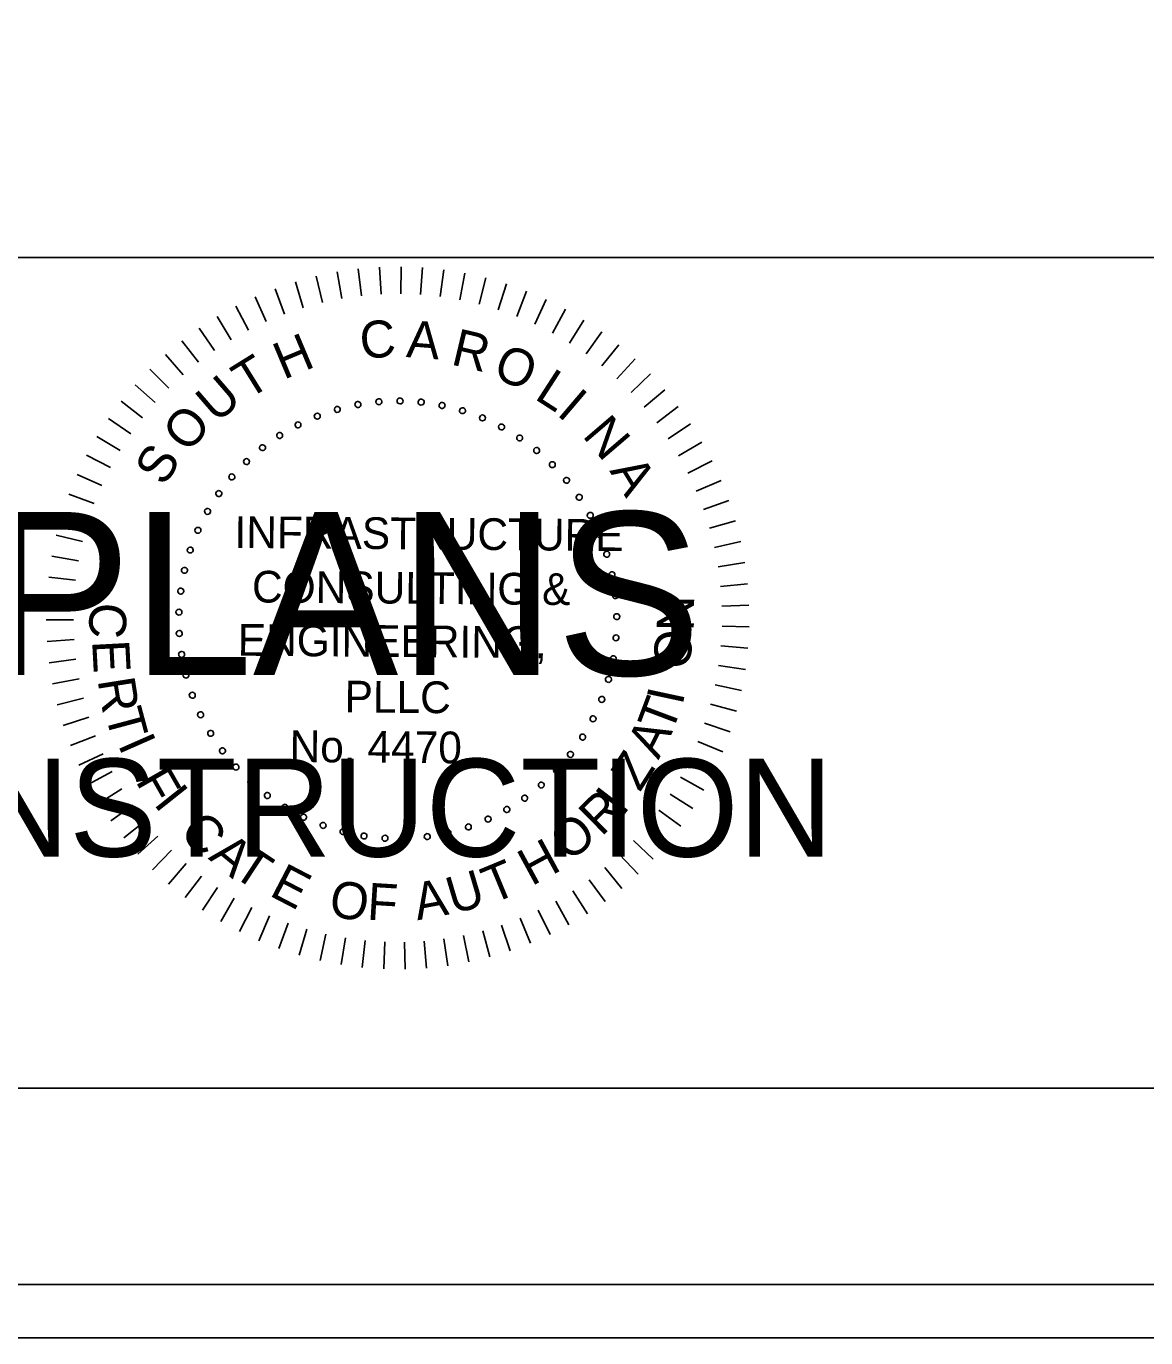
# Model space of a CAD drawing. Extents: x 967 to 1326, y 964 to 3144.
# Drawn here: x 1189.3 to 1212.88, y 2363.72 to 2391.36 of the extents above; entities that cross this region are included whole.
import ezdxf

# ---------------------------------------------------------------- set-up
doc = ezdxf.new("R2010")
doc.units = 0
for name, color, linetype in [('RD_XS_EwShp', 7, 'Continuous'), ('RD_XS_ExPaveRet', 7, 'Continuous'), ('RD_XS_TX_Elev_EX', 7, 'Continuous'), ('RD_XS_TX_Elev_PR', 7, 'Continuous'), ('RD_XS_TX_Station', 7, 'Continuous')]:
    doc.layers.add(name, color=color, linetype=linetype)

msp = doc.modelspace()

# ---------------------------------------------------------------- linework, layer by layer
at = {"layer": 'RD_XS_ExPaveRet'}
for points in [[(967.409, 2363.72), (1326.285, 2363.72), (1326.285, 2583.72), (967.409, 2583.72)], [(988.525, 2364.84), (1326.285, 2364.84), (1326.285, 2582.6), (988.525, 2582.6)]]:
    msp.add_lwpolyline(points, close=True, dxfattribs=at)
at = {"layer": 'RD_XS_TX_Elev_EX'}
for p, q in [((996.114, 2386.486), (1323.886, 2386.486)), ((1323.886, 2368.983), (996.114, 2368.983))]:
    msp.add_line(p, q, dxfattribs=at)
at = {"layer": 'RD_XS_TX_Elev_PR'}
for p, q in [((1195.846, 2386.181), (1195.945, 2385.62)), ((1196.292, 2386.245), (1196.357, 2385.68)), ((1196.742, 2386.282), (1196.772, 2385.714)), ((1197.194, 2386.292), (1197.189, 2385.723)), ((1197.645, 2386.274), (1197.606, 2385.706)), ((1198.094, 2386.228), (1198.02, 2385.664)), ((1198.54, 2386.156), (1198.432, 2385.596)), ((1194.968, 2385.971), (1195.134, 2385.427)), ((1195.403, 2386.09), (1195.536, 2385.536)), ((1198.98, 2386.056), (1198.838, 2385.504)), ((1199.414, 2385.929), (1199.238, 2385.387)), ((1194.122, 2385.656), (1194.353, 2385.136)), ((1194.54, 2385.827), (1194.739, 2385.293)), ((1199.839, 2385.777), (1199.63, 2385.246)), ((1200.253, 2385.598), (1200.013, 2385.082)), ((1193.715, 2385.461), (1193.978, 2384.956)), ((1200.656, 2385.395), (1200.385, 2384.894)), ((1193.321, 2385.241), (1193.614, 2384.752)), ((1201.047, 2385.167), (1200.745, 2384.684)), ((1192.94, 2384.997), (1193.263, 2384.528)), ((1201.422, 2384.917), (1201.092, 2384.453)), ((1192.576, 2384.731), (1192.926, 2384.282)), ((1201.781, 2384.643), (1201.424, 2384.2)), ((1192.228, 2384.443), (1192.605, 2384.016)), ((1202.124, 2384.349), (1201.739, 2383.928)), ((1191.899, 2384.134), (1192.301, 2383.731)), ((1202.447, 2384.034), (1202.038, 2383.638)), ((1191.589, 2383.805), (1192.015, 2383.428)), ((1202.751, 2383.7), (1202.318, 2383.329)), ((1191.299, 2383.459), (1191.748, 2383.108)), ((1203.034, 2383.348), (1202.579, 2383.004)), ((1191.032, 2383.095), (1191.501, 2382.772)), ((1203.294, 2382.979), (1202.82, 2382.664)), ((1190.787, 2382.716), (1191.274, 2382.422)), ((1203.532, 2382.595), (1203.04, 2382.31)), ((1190.565, 2382.323), (1191.07, 2382.059)), ((1203.746, 2382.198), (1203.237, 2381.943)), ((1190.368, 2381.916), (1190.888, 2381.684)), ((1203.936, 2381.788), (1203.412, 2381.564)), ((1190.196, 2381.499), (1190.729, 2381.299)), ((1204.1, 2381.367), (1203.563, 2381.176)), ((1190.05, 2381.072), (1190.594, 2380.905)), ((1204.238, 2380.937), (1203.691, 2380.779)), ((1189.93, 2380.636), (1190.484, 2380.503)), ((1204.349, 2380.5), (1203.794, 2380.375)), ((1189.837, 2380.195), (1190.398, 2380.095)), ((1204.434, 2380.056), (1203.872, 2379.966)), ((1189.771, 2379.748), (1190.337, 2379.683)), ((1204.491, 2379.608), (1203.925, 2379.552)), ((1189.732, 2379.298), (1190.301, 2379.267)), ((1204.522, 2379.158), (1203.953, 2379.137)), ((1189.721, 2378.847), (1190.29, 2378.851)), ((1204.524, 2378.706), (1203.955, 2378.72)), ((1189.737, 2378.396), (1190.306, 2378.434)), ((1204.499, 2378.256), (1203.932, 2378.304)), ((1189.781, 2377.946), (1190.346, 2378.019)), ((1204.447, 2377.807), (1203.884, 2377.89)), ((1189.852, 2377.5), (1190.412, 2377.608)), ((1204.367, 2377.363), (1203.81, 2377.479)), ((1189.951, 2377.06), (1190.502, 2377.201)), ((1204.261, 2376.924), (1203.712, 2377.074)), ((1190.076, 2376.626), (1190.617, 2376.8)), ((1204.128, 2376.492), (1203.589, 2376.676)), ((1190.227, 2376.2), (1190.757, 2376.408)), ((1203.969, 2376.07), (1203.442, 2376.286)), ((1190.403, 2375.785), (1190.92, 2376.024)), ((1190.605, 2375.381), (1191.106, 2375.651)), ((1203.784, 2375.658), (1203.271, 2375.906)), ((1203.574, 2375.258), (1203.078, 2375.537)), ((1190.831, 2374.99), (1191.315, 2375.291)), ((1203.341, 2374.871), (1202.862, 2375.18)), ((1191.081, 2374.614), (1191.545, 2374.943)), ((1203.085, 2374.5), (1202.626, 2374.837)), ((1191.353, 2374.253), (1191.796, 2374.61)), ((1191.646, 2373.91), (1192.067, 2374.293)), ((1202.806, 2374.145), (1202.368, 2374.509)), ((1191.96, 2373.585), (1192.356, 2373.994)), ((1202.506, 2373.807), (1202.092, 2374.197)), ((1192.293, 2373.28), (1192.664, 2373.712)), ((1202.186, 2373.488), (1201.796, 2373.903)), ((1192.644, 2372.996), (1192.988, 2373.45)), ((1201.847, 2373.19), (1201.484, 2373.628)), ((1193.011, 2372.734), (1193.327, 2373.208)), ((1201.491, 2372.912), (1201.155, 2373.372)), ((1193.394, 2372.495), (1193.68, 2372.987)), ((1200.731, 2372.425), (1200.453, 2372.922)), ((1201.119, 2372.657), (1200.811, 2373.136)), ((1193.791, 2372.279), (1194.047, 2372.788)), ((1194.2, 2372.088), (1194.424, 2372.612)), ((1200.331, 2372.217), (1200.083, 2372.73)), ((1194.62, 2371.923), (1194.812, 2372.459)), ((1195.05, 2371.783), (1195.208, 2372.33)), ((1199.495, 2371.877), (1199.312, 2372.416)), ((1199.918, 2372.034), (1199.702, 2372.561)), ((1195.487, 2371.67), (1195.612, 2372.225)), ((1195.93, 2371.584), (1196.021, 2372.146)), ((1196.377, 2371.524), (1196.434, 2372.091)), ((1196.828, 2371.493), (1196.85, 2372.062)), ((1197.279, 2371.488), (1197.267, 2372.058)), ((1197.73, 2371.512), (1197.683, 2372.079)), ((1198.179, 2371.562), (1198.097, 2372.126)), ((1198.624, 2371.64), (1198.508, 2372.198)), ((1199.063, 2371.745), (1198.913, 2372.295))]:
    msp.add_line(p, q, dxfattribs=at)
for centre, start, end in [((1196.285, 2383.388), 10.6038, 190.6038), ((1196.285, 2383.388), 190.6038, 10.6038), ((1196.727, 2383.447), 5.0653, 185.0653), ((1196.727, 2383.447), 185.0653, 5.0653), ((1197.172, 2383.464), 359.5268, 179.5268), ((1197.172, 2383.464), 179.5268, 359.5268), ((1197.617, 2383.438), 173.9884, 353.9884), ((1197.617, 2383.438), 353.9884, 173.9884), ((1198.057, 2383.369), 168.4499, 348.4499), ((1198.057, 2383.369), 348.4499, 168.4499), ((1195.429, 2383.142), 21.6807, 201.6807), ((1195.429, 2383.142), 201.6807, 21.6807), ((1195.851, 2383.285), 16.1422, 196.1422), ((1195.851, 2383.285), 196.1422, 16.1422), ((1198.489, 2383.258), 162.9114, 342.9114), ((1198.489, 2383.258), 342.9114, 162.9114), ((1198.908, 2383.106), 157.373, 337.373), ((1198.908, 2383.106), 337.373, 157.373), ((1195.023, 2382.958), 27.2191, 207.2191), ((1195.023, 2382.958), 207.2191, 27.2191), ((1199.31, 2382.914), 151.8345, 331.8345), ((1199.31, 2382.914), 331.8345, 151.8345), ((1194.637, 2382.736), 32.7576, 212.7576), ((1194.637, 2382.736), 212.7576, 32.7576), ((1199.692, 2382.684), 146.2961, 326.2961), ((1199.692, 2382.684), 326.2961, 146.2961), ((1194.274, 2382.478), 38.2961, 218.2961), ((1194.274, 2382.478), 218.2961, 38.2961), ((1200.05, 2382.419), 140.7576, 320.7576), ((1200.05, 2382.419), 320.7576, 140.7576), ((1193.937, 2382.186), 43.8345, 223.8345), ((1193.937, 2382.186), 223.8345, 43.8345), ((1200.38, 2382.12), 135.2191, 315.2191), ((1200.38, 2382.12), 315.2191, 135.2191), ((1193.63, 2381.862), 49.373, 229.373), ((1193.63, 2381.862), 229.373, 49.373), ((1200.68, 2381.79), 129.6807, 309.6807), ((1200.68, 2381.79), 309.6807, 129.6807), ((1193.356, 2381.511), 54.9114, 234.9114), ((1193.356, 2381.511), 234.9114, 54.9114), ((1200.947, 2381.433), 124.1422, 304.1422), ((1200.947, 2381.433), 304.1422, 124.1422), ((1193.117, 2381.135), 60.4499, 240.4499), ((1193.117, 2381.135), 240.4499, 60.4499), ((1201.179, 2381.052), 118.6038, 298.6038), ((1201.179, 2381.052), 298.6038, 118.6038), ((1192.915, 2380.737), 65.9884, 245.9884), ((1192.915, 2380.737), 245.9884, 65.9884), ((1201.372, 2380.651), 113.0653, 293.0653), ((1201.372, 2380.651), 293.0653, 113.0653), ((1192.753, 2380.322), 71.5268, 251.5268), ((1192.753, 2380.322), 251.5268, 71.5268), ((1201.526, 2380.233), 107.5268, 287.5268), ((1201.526, 2380.233), 287.5268, 107.5268), ((1192.632, 2379.894), 77.0653, 257.0653), ((1192.632, 2379.894), 257.0653, 77.0653), ((1201.638, 2379.801), 101.9884, 281.9884), ((1201.638, 2379.801), 281.9884, 101.9884), ((1192.552, 2379.455), 82.6038, 262.6038), ((1192.552, 2379.455), 262.6038, 82.6038), ((1201.709, 2379.361), 96.4499, 276.4499), ((1201.709, 2379.361), 276.4499, 96.4499), ((1192.515, 2379.011), 88.1422, 268.1422), ((1192.515, 2379.011), 268.1422, 88.1422), ((1201.737, 2378.917), 90.9114, 270.9114), ((1201.737, 2378.917), 270.9114, 90.9114), ((1192.522, 2378.565), 93.6807, 273.6807), ((1192.522, 2378.565), 273.6807, 93.6807), ((1201.721, 2378.471), 85.373, 265.373), ((1201.721, 2378.471), 265.373, 85.373), ((1192.571, 2378.122), 99.2191, 279.2191), ((1192.571, 2378.122), 279.2191, 99.2191), ((1201.663, 2378.029), 79.8345, 259.8345), ((1201.663, 2378.029), 259.8345, 79.8345), ((1192.662, 2377.686), 104.7576, 284.7576), ((1192.662, 2377.686), 284.7576, 104.7576), ((1201.563, 2377.595), 74.2961, 254.2961), ((1201.563, 2377.595), 254.2961, 74.2961), ((1192.796, 2377.261), 110.2961, 290.2961), ((1192.796, 2377.261), 290.2961, 110.2961), ((1201.42, 2377.173), 68.7576, 248.7576), ((1201.42, 2377.173), 248.7576, 68.7576), ((1192.97, 2376.851), 115.8345, 295.8345), ((1192.97, 2376.851), 295.8345, 115.8345), ((1201.238, 2376.766), 63.2191, 243.2191), ((1201.238, 2376.766), 243.2191, 63.2191), ((1193.182, 2376.459), 121.373, 301.373), ((1193.182, 2376.459), 301.373, 121.373), ((1201.018, 2376.379), 57.6807, 237.6807), ((1201.018, 2376.379), 237.6807, 57.6807), ((1193.432, 2376.09), 126.9114, 306.9114), ((1193.432, 2376.09), 306.9114, 126.9114), ((1200.761, 2376.014), 52.1422, 232.1422), ((1200.761, 2376.014), 232.1422, 52.1422), ((1193.715, 2375.746), 132.4499, 312.4499), ((1193.715, 2375.746), 312.4499, 132.4499), ((1200.47, 2375.677), 46.6038, 226.6038), ((1200.47, 2375.677), 226.6038, 46.6038), ((1194.031, 2375.431), 137.9884, 317.9884), ((1194.031, 2375.431), 317.9884, 137.9884), ((1200.148, 2375.369), 41.0653, 221.0653), ((1200.148, 2375.369), 221.0653, 41.0653), ((1194.376, 2375.149), 143.5268, 323.5268), ((1194.376, 2375.149), 323.5268, 143.5268), ((1199.798, 2375.093), 35.5268, 215.5268), ((1199.798, 2375.093), 215.5268, 35.5268), ((1194.746, 2374.901), 149.0653, 329.0653), ((1194.746, 2374.901), 329.0653, 149.0653), ((1199.422, 2374.853), 29.9884, 209.9884), ((1199.422, 2374.853), 209.9884, 29.9884), ((1195.139, 2374.69), 154.6038, 334.6038), ((1195.139, 2374.69), 334.6038, 154.6038), ((1195.55, 2374.517), 160.1422, 340.1422), ((1195.55, 2374.517), 340.1422, 160.1422), ((1198.611, 2374.486), 18.9114, 198.9114), ((1199.026, 2374.65), 24.4499, 204.4499), ((1199.026, 2374.65), 204.4499, 24.4499), ((1195.975, 2374.386), 165.6807, 345.6807), ((1195.975, 2374.386), 345.6807, 165.6807), ((1196.412, 2374.295), 171.2191, 351.2191), ((1196.412, 2374.295), 351.2191, 171.2191), ((1196.855, 2374.248), 356.7576, 176.7576), ((1197.301, 2374.243), 2.2961, 182.2961), ((1197.745, 2374.282), 7.8345, 187.8345), ((1197.745, 2374.282), 187.8345, 7.8345), ((1198.183, 2374.363), 13.373, 193.373), ((1198.183, 2374.363), 193.373, 13.373), ((1198.611, 2374.486), 198.9114, 18.9114), ((1196.855, 2374.248), 176.7576, 356.7576), ((1197.301, 2374.243), 182.2961, 2.2961)]:
    msp.add_arc(centre, 0.0627, start, end, dxfattribs=at)
at = {"layer": 'RD_XS_TX_Station'}
msp.add_lwpolyline([(967.409, 2363.72), (1326.285, 2363.72), (1326.285, 2583.72), (967.409, 2583.72)], close=True, dxfattribs=at)

# ---------------------------------------------------------------- texts
at = {"layer": 'RD_XS_EwShp'}
for s, height, p in [('FINAL PLANS', 3.4375, (1174.145, 2377.685)), ('NOT FOR CONSTRUCTION', 2.0625, (1170.901, 2373.86))]:
    msp.add_text(s, height=height, dxfattribs=at).set_placement(p)
at = {"layer": 'RD_XS_TX_Elev_PR'}
for s, height, rotation, p in [('C', 0.78, 4.7281, (1196.355, 2384.346)), ('A', 0.78, 355.6981, (1197.29, 2384.39)), ('H', 0.78, 22.7882, (1194.72, 2383.904)), ('R', 0.78, 346.6681, (1198.222, 2384.238)), ('O', 0.78, 337.638, (1199.096, 2383.972)), ('T', 0.78, 31.8182, (1193.961, 2383.478)), ('U', 0.78, 40.8482, (1193.306, 2382.976)), ('L', 0.78, 327.108, (1199.981, 2383.52)), ('I', 0.78, 319.578, (1200.451, 2383.182)), ('O', 0.78, 49.8782, (1192.707, 2382.341)), ('N', 0.78, 310.548, (1200.994, 2382.728)), ('S', 0.78, 58.9083, (1192.211, 2381.642)), ('A', 0.78, 301.5179, (1201.576, 2381.991)), ('INFRASTRUCTURE', 0.66873, 359.5268, (1193.682, 2380.367)), ('CONSULTING &', 0.66873, 359.5268, (1194.051, 2379.217)), ('N', 0.78, 89.2085, (1203.359, 2378.604)), ('C', 0.78, 267.025, (1190.646, 2379.227)), ('ENGINEERING,', 0.66873, 359.5268, (1193.751, 2378.095)), ('O', 0.78, 83.2085, (1203.26, 2377.786)), ('E', 0.78, 273.025, (1190.685, 2378.408)), ('R', 0.78, 279.025, (1190.799, 2377.583)), ('PLLC', 0.6687, 359.5268, (1196.002, 2376.9)), ('I', 0.78, 77.9093, (1203.121, 2377.032)), ('T', 0.78, 285.025, (1190.955, 2376.878)), ('T', 0.78, 69.3954, (1202.891, 2376.428)), ('No. 4470', 0.6687, 359.5268, (1194.843, 2375.855)), ('A', 0.78, 63.3954, (1202.616, 2375.888)), ('I', 0.78, 293.7713, (1191.221, 2376.225)), ('Z', 0.78, 57.3954, (1202.224, 2375.206)), ('F', 0.78, 299.7713, (1191.589, 2375.455)), ('I', 0.78, 308.5268, (1191.965, 2374.973)), ('R', 0.78, 44.5268, (1201.415, 2374.267)), ('I', 0.78, 52.3339, (1201.856, 2374.69)), ('C', 0.78, 314.5268, (1192.496, 2374.346)), ('O', 0.78, 38.5268, (1200.73, 2373.731)), ('A', 0.78, 320.5268, (1193.115, 2373.822)), ('T', 0.78, 326.5268, (1193.602, 2373.478)), ('H', 0.78, 28.5268, (1199.942, 2373.23)), ('E', 0.78, 332.5268, (1194.394, 2373.051)), ('T', 0.78, 22.5268, (1199.108, 2372.856)), ('U', 0.78, 16.5268, (1198.288, 2372.638)), ('O', 0.78, 350.5268, (1195.647, 2372.614)), ('F', 0.78, 356.5268, (1196.465, 2372.532)), ('A', 0.78, 10.5268, (1197.537, 2372.517))]:
    msp.add_text(s, height=height, rotation=rotation, dxfattribs=at).set_placement(p)

doc.saveas('drawing.dxf')
